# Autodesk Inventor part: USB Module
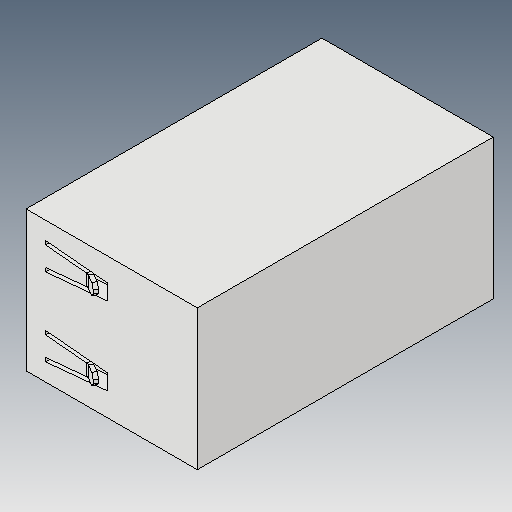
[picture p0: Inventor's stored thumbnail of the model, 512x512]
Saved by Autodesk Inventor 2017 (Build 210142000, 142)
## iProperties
Created: 2005-11
Part Number: USB Module
Material: Generic
Document SubType Name: Modeling
Designer: DanielSeverino
Density: 1 g/cm^3
Appearance: Default
Author: DanielSeverino
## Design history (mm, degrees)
feature "Solid1"
body "Solid2"
